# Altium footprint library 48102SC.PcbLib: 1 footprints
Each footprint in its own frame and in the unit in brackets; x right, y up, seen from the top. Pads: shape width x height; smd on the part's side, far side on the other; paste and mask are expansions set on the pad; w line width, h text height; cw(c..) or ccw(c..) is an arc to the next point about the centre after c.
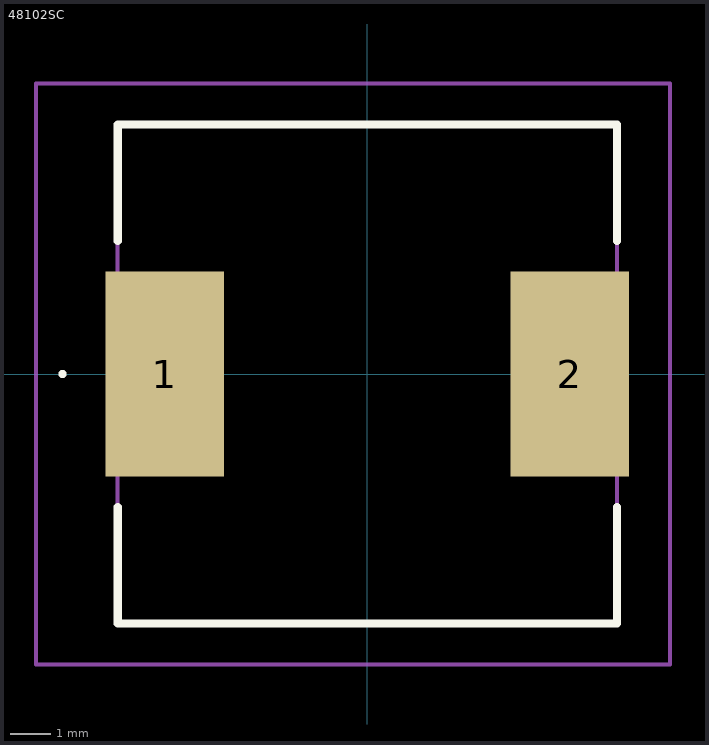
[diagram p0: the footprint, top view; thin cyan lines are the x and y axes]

## 48102SC [mm]
pads (2):
  rect 2.9x5 smd: 1(-4.95,0) 2(4.95,0)
Top Overlay:
  lines w0.1: -7.5,0 -7.5,0 ; -7.5,0 ccw(c-7.45,0) -7.4,0 ; -7.5,0 cw(c-7.45,0) -7.4,0 ; -7.4,0 -7.4,0
  lines w0.2: -6.1,-3.25 -6.1,-6.1 6.1,-6.1 6.1,-3.25 ; -6.1,3.25 -6.1,6.1 6.1,6.1 6.1,3.25
Mechanical 15:
  lines w0.1: -6.1,-6.1 6.1,-6.1 6.1,6.1 -6.1,6.1 -6.1,-6.1
Mechanical 20:
  lines w0.1: -8.1,-7.1 7.4,-7.1 7.4,7.1 -8.1,7.1 -8.1,-7.1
